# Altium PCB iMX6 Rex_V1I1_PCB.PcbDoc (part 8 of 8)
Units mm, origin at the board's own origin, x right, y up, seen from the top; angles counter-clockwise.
Board outline 70 x 40 mm, 12 copper layers (L1, L2, L3, L4, L5 (PWR), L6 (PWR), L7 (PWR), L8 (PWR), L9, L10, L11, L12), stack 1.566 mm thick; 473 components, 409 nets, 2294 pads, 1880 vias.
Unrouted connection lines stored in the file: 7.
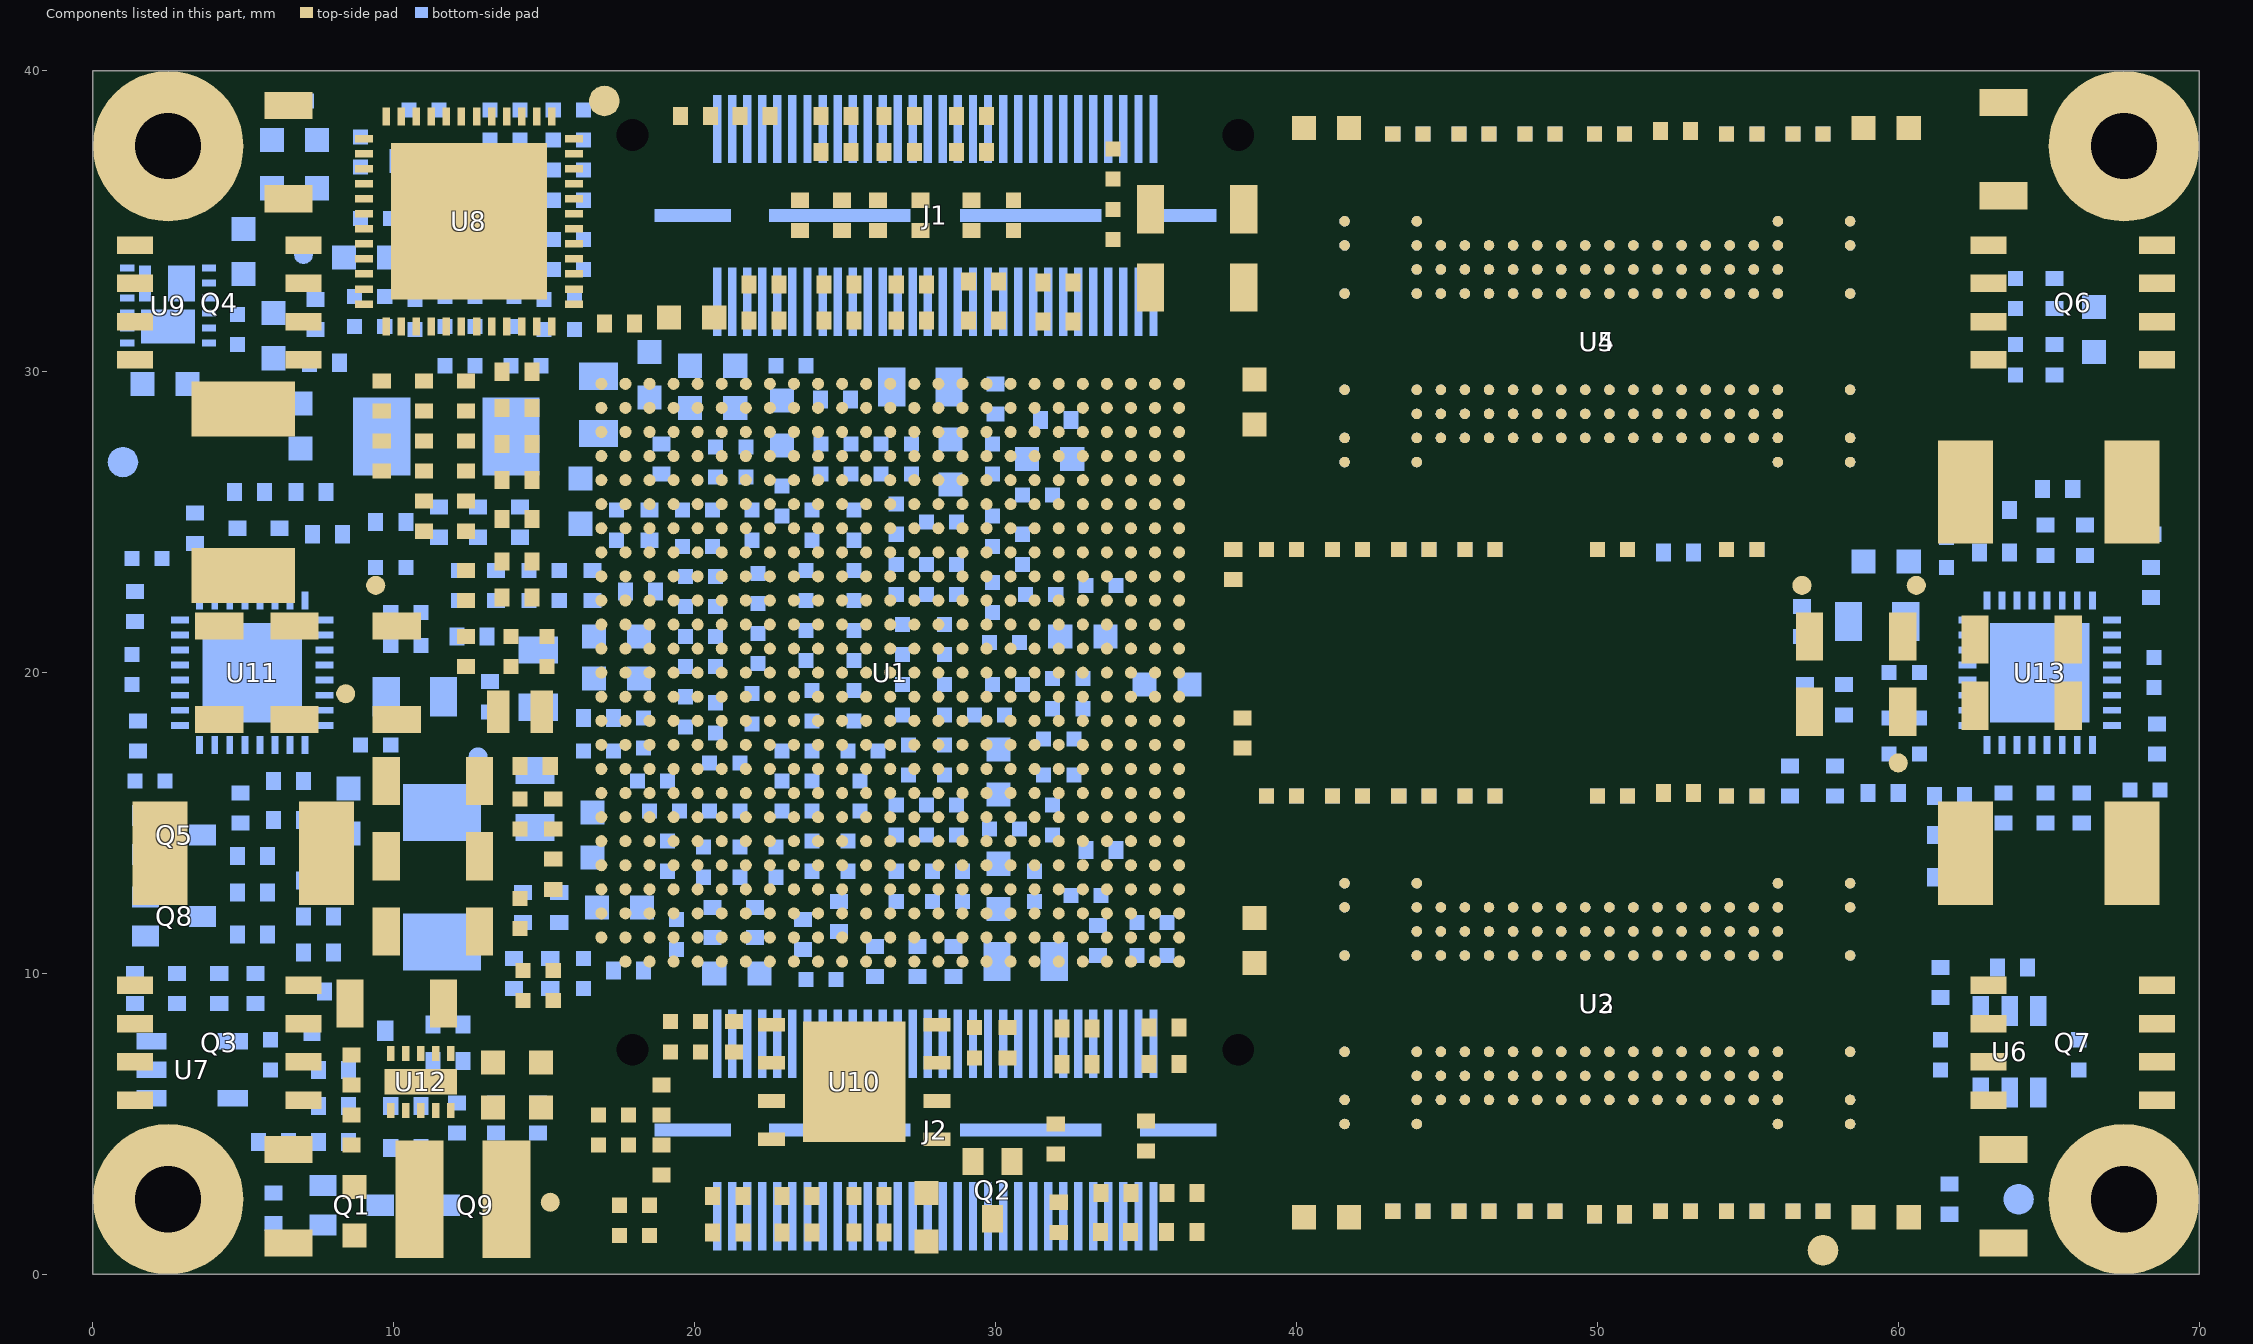
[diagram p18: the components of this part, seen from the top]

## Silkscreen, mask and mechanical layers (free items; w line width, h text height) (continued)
Manufacturing Notes:
  lines w0.2: 101.324,8.28 171.85,8.28 ; 101.324,12.17 171.85,12.17 ; 99.8,-45.65 ccw(c101.05,-45.65) 101.05,-46.9 170.6,-46.9 ccw(c170.6,-45.65) 171.85,-45.65 171.85,16.65 ccw(c170.6,16.65) 170.6,17.9 101.05,17.9 ccw(c101.05,16.65) 99.8,16.65 99.8,-45.65
  lines w0.254: 0,-47.5 80,-47.5 ; 0,-47.425 0,-37.425 ; 0,-27.5 80,-27.5 ; 40,-37.5 40,-27.5 ; 62.5,-27.5 62.5,-20 ; 80,-47.425 80,-37.425 ; 0,-37.5 0,-20 80,-20 80,-37.5 0,-37.5
  text "Board info" at 92.754,120.254 h1.52
  text "Minimum Track: 80um" at 92.754,117.754 h1.52
  text "Minimum Gap: 75um" at 92.754,115.254 h1.52
  text "Minimum Through Hole VIA: 0.45mm (pad) / 0.2mm (drill). Drilling: L1-L12" at 92.754,112.754 h1.52
  text "uVIA: 0.27mm (pad) / 0.1mm (laser drilled hole). Drilling: L1-L2, L2-L3, L10-L11, L11-L12" at 92.754,110.254 h1.52
  text "Buried VIA: 0.45mm (pad) / 0.2mm (drill). Driling: L3-L10" at 92.754,107.754 h1.52
  text "Files" at 0,107.5 h1.52
  text "*.GTO - Top Overlay" at 0,105 h1.52
  text "*.GTP - Top Paste" at 0,102.5 h1.52
  text "1. REMOVE ALL NON-FUNCTIONAL INNER LAYER PADS." at 92.754,100.254 h1.52
  text "*.GTS - Top Solder" at 0,100 h1.52
  text "*.GTL - L1 (Positive)" at 0,97.5 h1.52
  text "2. THIS BOARD CONTAINS IMPEDANCE CONTROLLED TRACKS, TRACK AND GAP SIZES ARE AS FOLLOWS:" at 92.754,95.254 h1.52
  text "*.G1 - L2 (Positive)" at 0,95 h1.52
  text "*.G2 - L3 (Positive)" at 0,92.5 h1.52
  text "TYPE;" at 97.754,90.254 h1.52
  text "Impedance;" at 110.254,90.254 h1.52
  text "Layer (Reference);" at 132.754,90.254 h1.52
  text "Width (um);" at 167.754,90.254 h1.52
  text "Gap (um);" at 187.754,90.254 h1.52
  text "*.GP1 - L4 (Negative)" at 0,90 h1.52
  text "*.G3 - L5 (Positive)" at 0,87.5 h1.52
  text "DIFF;" at 97.754,85.254 h1.52
  text "90ohm;" at 110.254,85.254 h1.52
  text "L1(L2), L12(L11);" at 132.754,85.254 h1.52
  text "101" at 167.754,85.254 h1.52
  text "114" at 187.754,85.254 h1.52
  text "*.G4 - L6 (Positive)" at 0,85 h1.52
  text "DIFF;" at 97.754,82.754 h1.52
  text "90ohm;" at 110.254,82.754 h1.52
  text "L3(L2,L4), L10(L9,L11)" at 132.754,82.754 h1.52
  text "85" at 167.754,82.754 h1.52
  text "115" at 187.754,82.754 h1.52
  text "*.G5 - L7 (Positive)" at 0,82.5 h1.52
  text "*.G6 - L8 (Positive)" at 0,80 h1.52
  text "DIFF;" at 97.754,77.754 h1.52
  text "100ohm;" at 110.254,77.754 h1.52
  text "L1(L2), L12(L11);" at 132.754,77.754 h1.52
  text "90" at 167.754,77.754 h1.52
  text "160" at 187.754,77.754 h1.52
  text "*.GP2 - L9 (Negative)" at 0,77.5 h1.52
  text "DIFF;" at 97.754,75.254 h1.52
  text "100ohm;" at 110.254,75.254 h1.52
  text "L3(L2,L4), L10(L9,L11)" at 132.754,75.254 h1.52
  text "85" at 167.754,75.254 h1.52
  text "195" at 187.754,75.254 h1.52
  text "*.G7 - L10 (Positive)" at 0,75 h1.52
  text "*.G8 - L11 (Positive)" at 0,72.5 h1.52
  text "SE;" at 97.754,70.254 h1.52
  text "55ohm;" at 110.254,70.254 h1.52
  text "L1(L2), L12(L11);" at 132.754,70.254 h1.52
  text "93" at 167.754,70.254 h1.52
  text "*.GBL - L12 (Positive)" at 0,70 h1.52
  text "SE;" at 97.754,67.754 h1.52
  text "55ohm;" at 110.254,67.754 h1.52
  text "L3(L2,L4), L10(L9,L11)" at 132.754,67.754 h1.52
  text "80" at 167.754,67.754 h1.52
  text "*.GBS - Bottom Solder" at 0,67.5 h1.52
  text "*.GBP - Bottom Paste" at 0,65 h1.52
  text "3. FINISHED PANEL THICKNESS IS NOT CRITICAL: TO BE APPROXIMATELY 1.6mm" at 92.754,62.754 h1.52
  text "*.GBO - Bottom Overlay" at 0,62.5 h1.52
  text "*.GM2 - Mechanical Drawing" at 0,60 h1.52
  text "4. BOARD FINISH: IMMERSION Au/ELECTROLESS Ni; 0.05-0.12 um GOLD; 3-6um NICKEL" at 92.754,57.754 h1.52
  text "*.GM3 - Manufacturing Notes" at 0,57.5 h1.52
  text "*.GM4 - Licence" at 0,55 h1.52
  text "5. SOLDER RESIST: APPLY TO BOTH SIDES COLOUR - DARK BLUE" at 92.754,52.754 h1.52
  text "*.GM28 - Board Outline" at 0,52.5 h1.52
  text "6. COMPONENT IDENT: COLOUR TO BE WHITE" at 92.754,47.754 h1.52
  text "7. PANELIZE THE BOARD (2PCS PER PANEL). PLACE FIDUCIALS ON THE PANEL STRIPS AS FOLLOWS:" at 92.754,42.754 h1.52
  text "- FIDUCIAL DIAMTER 1-1.5MM, SOLDER MASK OPENING AT LEAST 1MM GREATER THAN FIDUCIAL" at 97.754,40.254 h1.52
  text "- MINIMUM 4MM DISTANCE FROM THE PANEL EDGE" at 97.754,37.754 h1.52
  text "- 3 FIDUCIALS SHOULD LIE ON TWO LINES THAT INTERSECT AT A RIGHT ANGLE" at 97.754,35.254 h1.52
  text "FOR MASS PRODUCTION" at 8.8,33 h3
  text "- PLACE ONE FIDUCIAL INTO EACH PANEL CORNER (FOUR ON THE TOP AND FOUR ON THE BOTTOM LAYER)" at 97.754,32.754 h1.52
  text "READ THE LICENCE" at 12.7,22.9 h3
  text "Layer Stack Up Detail" at 101.324,13.375 h2.2
  text "CONTACT US AT" at 16.6,12.8 h3
  text "Layer" at 101.324,10.72 h0.9
  text "Gerber" at 126.626,10.72 h0.9
  text "Copper" at 139.941,10.72 h0.9
  text "Dielectric" at 154.727,10.72 h0.9
  text "Name" at 101.324,8.92 h0.9
  text "Document" at 126.626,8.92 h0.9
  text "Thickness" at 139.941,8.92 h0.9
  text "Height" at 154.727,8.92 h0.9
  text "Top Solder Mask" at 101.324,6.386 h1.25
  text "(.GTS)" at 126.626,6.386 h1.25
  text "L1" at 101.324,2.799 h1.25
  text "(.GTL)" at 126.626,2.799 h1.25
  text "0.038mm" at 139.941,2.799 h1.25
  text "robert.feranec@fedevel.com" at -1.5,2.7 h3
  text "0.07mm" at 154.727,1.006 h1.25
  text "L2" at 101.324,-0.788 h1.25
  text "(.G1)" at 126.626,-0.788 h1.25
  text "0.038mm" at 139.941,-0.788 h1.25
  text "0.092mm" at 154.727,-2.581 h1.25
  text "L3" at 101.324,-4.375 h1.25
  text "(.G2)" at 126.626,-4.375 h1.25
  text "0.038mm" at 139.941,-4.375 h1.25
  text "0.2mm" at 154.727,-6.169 h1.25
  text "L4" at 101.324,-7.962 h1.25
  text "(.GP1)" at 126.626,-7.962 h1.25
  text "0.015mm" at 139.941,-7.962 h1.25
  text "0.102mm" at 154.727,-9.756 h1.25
  text "L5" at 101.324,-11.549 h1.25
  text "(.G3)" at 126.626,-11.549 h1.25
  text "0.015mm" at 139.941,-11.549 h1.25
  text "0.1mm" at 154.727,-13.343 h1.25
  text "L6" at 101.324,-15.136 h1.25
  text "(.G4)" at 126.626,-15.136 h1.25
  text "0.015mm" at 139.941,-15.136 h1.25
  text "0.118mm" at 154.727,-16.93 h1.25
  text "L7" at 101.324,-18.724 h1.25
  text "(.G5)" at 126.626,-18.724 h1.25
  text "0.015mm" at 139.941,-18.724 h1.25
  text "0.1mm" at 154.727,-20.517 h1.25
  text "L8" at 101.324,-22.311 h1.25
  text "(.G6)" at 126.626,-22.311 h1.25
  text "0.015mm" at 139.941,-22.311 h1.25
  text "0.102mm" at 154.727,-24.104 h1.25
  text "iMX6 Rex Module" at 5,-25 h3
  text ".VersionRevision" at 65,-25 h3
  text "L9" at 101.324,-25.898 h1.25
  text "(.GP2)" at 126.626,-25.898 h1.25
  text "0.015mm" at 139.941,-25.898 h1.25
  text "0.2mm" at 154.727,-27.691 h1.25
  text "L10" at 101.324,-29.485 h1.25
  text "(.G7)" at 126.626,-29.485 h1.25
  text "0.038mm" at 139.941,-29.485 h1.25
  text "0.093mm" at 154.727,-31.279 h1.25
  text "Copyright FEDEVEL 2013" at 5,-32.5 h1.52
  text "Designed by FEDEVEL" at 45,-32.5 h1.52
  text "L11" at 101.324,-33.072 h1.25
  text "(.G8)" at 126.626,-33.072 h1.25
  text "0.038mm" at 139.941,-33.072 h1.25
  text "0.071mm" at 154.727,-34.866 h1.25
  text "www.fedevel.com" at 45,-35 h1.52
  text "L12" at 101.324,-36.659 h1.25
  text "(.GBL)" at 126.626,-36.659 h1.25
  text "0.038mm" at 139.941,-36.659 h1.25
  text "Bottom Solder Mask" at 101.324,-40.246 h1.25
  text "(.GBS)" at 126.626,-40.246 h1.25
  text "Contact:" at 5,-42.5 h1.52
  text "robert.feranec@fedevel.com" at 5,-45 h1.52
Licence:
  text "LICENCE" at 92.6,124.8 h1.52
  text "ORIGINAL AUTHOR: FEDEVEL 2013" at 92.8,120.3 h1.52
  text "WEBSITE: http://www.iMX6Rex.com" at 92.8,117.8 h1.52
  text "This is a human-readable summary of the Legal Code (read full licence at:" at 92.8,112.8 h1.52
  text "http://creativecommons.org/licenses/by-nc-nd/3.0/deed.en_GB)." at 92.8,110.3 h1.52
  text "You are free:" at 92.8,105.3 h1.52
  text "to copy, distribute, display, and perform the work" at 92.8,102.8 h1.52
  text "Under the following conditions:" at 92.8,97.8 h1.52
  text "Attribution - You must give the original author credit." at 92.8,95.3 h1.52
  text "Non-Commercial - You may not use this work for commercial purposes." at 92.8,92.8 h1.52
  text "No Derivative Works - You may not alter, transform, or build upon this work." at 92.8,90.3 h1.52
  text "With the understanding that:" at 92.8,85.3 h1.52
  text "Waiver - Any of the above conditions can be waived if you get permission from the copyright holder." at 92.8,82.8 h1.52
  text "Public Domain - Where the work or any of its elements is in the public domain under applicable law, that status is in no way affected by the licence." at 92.8,80.3 h1.52
  text "Other Rights - In no way are any of the following rights affected by the licence:" at 92.8,77.8 h1.52
  text "- Your fair dealing or fair use rights, or other applicable copyright exceptions and limitations;" at 92.8,75.3 h1.52
  text "- The author's moral rights;" at 92.8,72.8 h1.52
  text "- Rights other persons may have either in the work itself or in how the work is used, such as publicity or privacy rights." at 92.8,70.3 h1.52
  text "Notice - For any reuse or distribution, you must make clear to others the licence terms of this work." at 92.8,65.3 h1.52
Board Outline:
  the board outline again, w0.2
ASM Top:
  text "Assembly TOP of iMX6 Rex Module" at 8,47.5 h1.52
  text ".VersionRevision" at 56.8,47.5 h1.52
  text ".VariantName" at 25.7,43.6 h1.52
ASM Bottom:
  text ".VersionRevision" at 9.6,47.5 h1.52
  text "Assembly BOTTOM of iMX6 Rex Module" at 62.5,47.4 h1.52
  text ".VariantName" at 41.7,43.6 h1.52

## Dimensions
0,0 to 0,40 on Mechanical Drawing
2.5,2.5 to 0,0 on Mechanical Drawing
2.5,2.5 to 67.5,2.5 on Mechanical Drawing
67.5,37.5 to 72.9,40.7 on Mechanical Drawing
40.065,7.47 to -0.5,2.5 on Mechanical Drawing
40.065,37.87 to 40.065,7.47 on Mechanical Drawing
67.5,37.5 to 67.5,2.5 on Mechanical Drawing
0,0 to 70,0 on Mechanical Drawing
0,0 to 2.5,-0.5 on Mechanical Drawing
17.935,39.1 to 2.5,2.5 on Mechanical Drawing
17.935,37.9 to 38.065,39.07 on Mechanical Drawing
38.065,37.87 to 44.6,43.1 on Mechanical Drawing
